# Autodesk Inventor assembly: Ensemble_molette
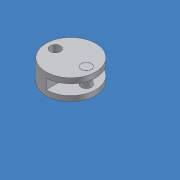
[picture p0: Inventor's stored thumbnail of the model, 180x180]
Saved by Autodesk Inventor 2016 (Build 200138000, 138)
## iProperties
Shininess: 64.0
Length Units: 11269
Angle Units: 11279
Time Units: 11290
Mass Units: 11283
Length Display Precision: 3
Angle Display Precision: 2
Compacted: True
Created: 2003-07
Part Number: Ensemble_molette
Document SubType Name: Assembly
Designer: trameau
Density: 0.0
Volumn: 0.0
Area: 0.0
PropertySet Name: Model Information
Control State: 0
Master: False
Checked Out: False
Author: trameau
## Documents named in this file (3)
- G:\Consmec\1si\Cours\Leçon 05 - Statique\05-04-Statique avec frottement\06-02 Exercices statique Frottement\28-02 Exercices statique Frottement\28-02-02 Exercice stat frottement 2\06-02-02-2 Dessin 3d pincetole\Ensemble_molette.iam
- G:\Consmec\1si\Cours\Leçon 05 - Statique\05-04-Statique avec frottement\06-02 Exercices statique Frottement\28-02 Exercices statique Frottement\28-02-02 Exercice stat frottement 2\06-02-02-2 Dessin 3d pincetole\molette.ipt
- G:\Consmec\1si\Cours\Leçon 05 - Statique\05-04-Statique avec frottement\06-02 Exercices statique Frottement\28-02 Exercices statique Frottement\28-02-02 Exercice stat frottement 2\06-02-02-2 Dessin 3d pincetole\axe_10x20.ipt
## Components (2 placed, 2 different names)
1. molette:1 — Logement:1
2. axe_10x20:1 — Logement:1
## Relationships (1: Insert 1)
- Logement:1 [Insert]: molette:1 ↔ axe_10x20:1
